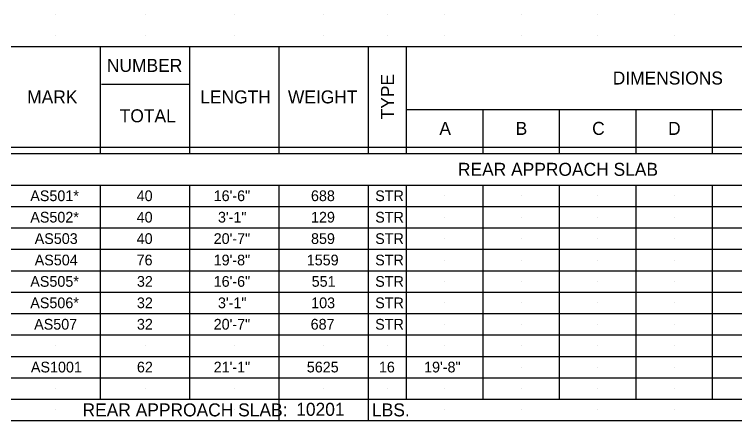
# Model space of a CAD drawing. Extents: x 0 to 34, y 0 to 22.
# Drawn here: x 16.8 to 26.21, y 9.38 to 14.69 of the extents above; entities that cross this region are included whole.
import ezdxf

# ---------------------------------------------------------------- set-up
doc = ezdxf.new("R2010")
doc.units = 0
doc.layers.add('BR_P_Gen_Text', color=7, linetype='Continuous')

msp = doc.modelspace()

# ---------------------------------------------------------------- linework, layer by layer
at = {"layer": 'BR_P_Gen_Text'}
for p, q in [((17.3435, 14.6926), (17.3435, 14.6926)), ((17.3435, 14.6926), (17.3435, 14.6926)), ((18.5102, 14.6926), (18.5102, 14.6926)), ((18.5102, 14.6926), (18.5102, 14.6926)), ((19.6769, 14.6926), (19.6769, 14.6926)), ((19.6769, 14.6926), (19.6769, 14.6926)), ((20.8437, 14.6927), (20.8437, 14.6927)), ((20.8437, 14.6927), (20.8437, 14.6927)), ((21.677, 14.6926), (21.677, 14.6926)), ((21.677, 14.6926), (21.677, 14.6926)), ((22.427, 14.6926), (22.427, 14.6926)), ((22.427, 14.6926), (22.427, 14.6926)), ((23.427, 14.6926), (23.427, 14.6926)), ((23.427, 14.6926), (23.427, 14.6926)), ((24.427, 14.6926), (24.427, 14.6926)), ((24.427, 14.6926), (24.427, 14.6926)), ((25.427, 14.6926), (25.427, 14.6926)), ((25.427, 14.6926), (25.427, 14.6926)), ((17.3435, 14.4126), (17.3435, 14.4126)), ((17.3435, 14.4126), (17.3435, 14.4126)), ((18.5102, 14.4126), (18.5102, 14.4126)), ((18.5102, 14.4126), (18.5102, 14.4126)), ((19.6769, 14.4126), (19.6769, 14.4126)), ((19.6769, 14.4126), (19.6769, 14.4126)), ((20.8436, 14.4127), (20.8436, 14.4127)), ((20.8437, 14.4127), (20.8437, 14.4127)), ((21.677, 14.4126), (21.677, 14.4126)), ((21.677, 14.4126), (21.677, 14.4126)), ((22.427, 14.4126), (22.427, 14.4126)), ((23.427, 14.4126), (23.427, 14.4126)), ((24.427, 14.4126), (24.427, 14.4126)), ((25.427, 14.4126), (25.427, 14.4126)), ((16.7602, 14.2725), (31.927, 14.2726)), ((17.9269, 12.8725), (17.9269, 14.2725)), ((19.0936, 12.8723), (19.0936, 14.2725)), ((20.2602, 12.8725), (20.2603, 14.2725)), ((21.427, 12.8726), (21.427, 14.2725)), ((21.927, 12.8726), (21.927, 14.2725)), ((17.9407, 13.7784), (19.0936, 13.7784)), ((21.927, 13.449), (28.927, 13.4491)), ((22.927, 12.8724), (22.927, 13.4491)), ((23.927, 12.8724), (23.927, 13.4491)), ((24.927, 12.8723), (24.927, 13.4491)), ((25.927, 12.8724), (25.927, 13.4491)), ((16.7602, 12.9548), (31.927, 12.9549)), ((16.7602, 12.8725), (31.927, 12.8725)), ((22.8436, 12.6666), (22.8436, 12.6666)), ((16.7602, 12.4608), (31.927, 12.4609)), ((17.9269, 9.6608), (17.9269, 12.4608)), ((19.0936, 9.6608), (19.0936, 12.4608)), ((20.2603, 9.3808), (20.2602, 12.4608)), ((21.427, 9.3808), (21.427, 12.4609)), ((21.927, 9.6608), (21.927, 12.4609)), ((22.9269, 9.6608), (22.927, 12.4608)), ((23.927, 9.6608), (23.927, 12.4608)), ((24.927, 9.6608), (24.927, 12.4608)), ((25.927, 9.6608), (25.927, 12.4608)), ((17.3435, 12.3208), (17.3435, 12.3208)), ((18.5102, 12.3208), (18.5102, 12.3208)), ((19.6769, 12.3209), (19.6769, 12.3209)), ((20.8437, 12.3209), (20.8437, 12.3209)), ((21.677, 12.3208), (21.677, 12.3208)), ((22.427, 12.3208), (22.427, 12.3208)), ((23.427, 12.3208), (23.427, 12.3208)), ((24.427, 12.3208), (24.427, 12.3208)), ((25.427, 12.3208), (25.427, 12.3208)), ((16.7602, 12.1808), (31.927, 12.1808)), ((17.3435, 12.0408), (17.3435, 12.0408)), ((18.5102, 12.0408), (18.5102, 12.0408)), ((19.6769, 12.0409), (19.6769, 12.0409)), ((20.8437, 12.0409), (20.8437, 12.0409)), ((21.677, 12.0408), (21.677, 12.0408)), ((22.427, 12.0408), (22.427, 12.0408)), ((23.427, 12.0408), (23.427, 12.0408)), ((24.427, 12.0408), (24.427, 12.0408)), ((25.427, 12.0408), (25.427, 12.0408)), ((16.7602, 11.9008), (31.927, 11.9008)), ((17.3435, 11.7608), (17.3435, 11.7608)), ((18.5102, 11.7608), (18.5102, 11.7608)), ((19.6769, 11.7608), (19.6769, 11.7608)), ((20.8437, 11.7609), (20.8437, 11.7609)), ((21.677, 11.7608), (21.677, 11.7608)), ((22.427, 11.7608), (22.427, 11.7608)), ((23.427, 11.7608), (23.427, 11.7608)), ((24.427, 11.7608), (24.427, 11.7608)), ((25.427, 11.7608), (25.427, 11.7608)), ((16.7602, 11.6208), (31.927, 11.6208)), ((17.3435, 11.4808), (17.3435, 11.4808)), ((22.427, 11.4808), (22.427, 11.4808)), ((23.427, 11.4808), (23.427, 11.4808)), ((24.427, 11.4808), (24.427, 11.4808)), ((25.427, 11.4808), (25.427, 11.4808)), ((16.7602, 11.3408), (31.927, 11.3408)), ((17.3435, 11.2008), (17.3435, 11.2008)), ((18.5102, 11.2008), (18.5102, 11.2008)), ((19.6769, 11.2008), (19.6769, 11.2008)), ((20.8437, 11.2009), (20.8437, 11.2009)), ((21.677, 11.2008), (21.677, 11.2008)), ((22.427, 11.2008), (22.427, 11.2008)), ((23.427, 11.2008), (23.427, 11.2008)), ((24.427, 11.2008), (24.427, 11.2008)), ((25.427, 11.2008), (25.427, 11.2008)), ((16.7602, 11.0608), (31.927, 11.0608)), ((17.3435, 10.9208), (17.3435, 10.9208)), ((18.5102, 10.9208), (18.5102, 10.9208)), ((19.6769, 10.9208), (19.6769, 10.9208)), ((20.8437, 10.9209), (20.8437, 10.9209)), ((21.677, 10.9208), (21.677, 10.9208)), ((22.427, 10.9208), (22.427, 10.9208)), ((23.427, 10.9208), (23.427, 10.9208)), ((24.427, 10.9208), (24.427, 10.9208)), ((25.427, 10.9208), (25.427, 10.9208)), ((16.7602, 10.7808), (31.927, 10.7809)), ((17.3435, 10.6408), (17.3435, 10.6408)), ((18.5102, 10.6408), (18.5102, 10.6408)), ((19.6769, 10.6408), (19.6769, 10.6408)), ((20.8437, 10.6409), (20.8437, 10.6409)), ((21.677, 10.6408), (21.677, 10.6408)), ((22.427, 10.6408), (22.427, 10.6408)), ((23.427, 10.6408), (23.427, 10.6408)), ((24.427, 10.6408), (24.427, 10.6408)), ((25.427, 10.6408), (25.427, 10.6408)), ((16.7602, 10.5008), (31.927, 10.5009)), ((17.3435, 10.3608), (17.3435, 10.3608)), ((17.3435, 10.3608), (17.3435, 10.3608)), ((18.5102, 10.3608), (18.5102, 10.3608)), ((18.5102, 10.3608), (18.5102, 10.3608)), ((19.6769, 10.3608), (19.6769, 10.3608)), ((19.6769, 10.3608), (19.6769, 10.3608)), ((20.8437, 10.3609), (20.8437, 10.3609)), ((20.8437, 10.3609), (20.8437, 10.3609)), ((21.677, 10.3608), (21.677, 10.3608)), ((21.677, 10.3608), (21.677, 10.3608)), ((22.427, 10.3608), (22.427, 10.3608)), ((22.427, 10.3608), (22.427, 10.3608)), ((23.427, 10.3608), (23.427, 10.3608)), ((23.427, 10.3608), (23.427, 10.3608)), ((24.427, 10.3608), (24.427, 10.3608)), ((24.427, 10.3608), (24.427, 10.3608)), ((25.427, 10.3608), (25.427, 10.3608)), ((25.427, 10.3608), (25.427, 10.3608)), ((16.7602, 10.2208), (31.927, 10.2209)), ((17.3435, 10.0808), (17.3435, 10.0808)), ((17.3435, 10.0808), (17.3435, 10.0808)), ((18.5102, 10.0808), (18.5102, 10.0808)), ((18.5102, 10.0808), (18.5102, 10.0808)), ((19.6769, 10.0808), (19.6769, 10.0808)), ((19.6769, 10.0808), (19.6769, 10.0808)), ((20.8437, 10.0809), (20.8437, 10.0809)), ((20.8437, 10.0809), (20.8437, 10.0809)), ((21.677, 10.0808), (21.677, 10.0808)), ((21.677, 10.0808), (21.677, 10.0808)), ((22.427, 10.0808), (22.427, 10.0808)), ((22.427, 10.0808), (22.427, 10.0808)), ((23.427, 10.0808), (23.427, 10.0808)), ((23.427, 10.0808), (23.427, 10.0808)), ((24.427, 10.0808), (24.427, 10.0808)), ((24.427, 10.0808), (24.427, 10.0808)), ((25.427, 10.0808), (25.427, 10.0808)), ((25.427, 10.0808), (25.427, 10.0808)), ((16.7602, 9.9408), (31.927, 9.9409)), ((17.3435, 9.8008), (17.3435, 9.8008)), ((18.5102, 9.8008), (18.5102, 9.8008)), ((19.6769, 9.8008), (19.6769, 9.8008)), ((20.8437, 9.8009), (20.8437, 9.8009)), ((21.677, 9.8008), (21.677, 9.8008)), ((22.427, 9.8008), (22.427, 9.8008)), ((23.427, 9.8008), (23.427, 9.8008)), ((24.427, 9.8008), (24.427, 9.8008)), ((25.427, 9.8008), (25.427, 9.8008)), ((16.7602, 9.6608), (31.927, 9.6608)), ((17.3435, 9.5208), (17.3435, 9.5208)), ((18.5102, 9.5208), (18.5102, 9.5208)), ((19.6769, 9.5208), (19.6769, 9.5208)), ((20.8437, 9.5209), (20.8437, 9.5209)), ((21.677, 9.5208), (21.677, 9.5208)), ((22.427, 9.5208), (22.427, 9.5208)), ((23.427, 9.5208), (23.427, 9.5208)), ((24.427, 9.5208), (24.427, 9.5208)), ((25.427, 9.5208), (25.427, 9.5208)), ((16.7602, 9.3808), (31.927, 9.3808))]:
    msp.add_line(p, q, dxfattribs=at)

# ---------------------------------------------------------------- texts
for s, height, p in [('NUMBER', 0.17, (18.0101, 13.9404)), ('DIMENSIONS', 0.17, (24.6212, 13.7758)), ('MARK', 0.17, (16.9678, 13.5287)), ('LENGTH', 0.17, (19.2303, 13.5287)), ('WEIGHT', 0.17, (20.3758, 13.5287)), ('TOTAL', 0.17, (18.1771, 13.2816)), ('A', 0.17, (22.3553, 13.117)), ('B', 0.17, (23.3522, 13.117)), ('C', 0.17, (24.3522, 13.117)), ('D', 0.17, (25.3449, 13.117)), ('REAR APPROACH SLAB', 0.17, (22.5978, 12.5817)), ('AS501*', 0.14, (17.0085, 12.2508)), ('40', 0.14, (18.3988, 12.2508)), ('16\'-6"', 0.14, (19.4055, 12.2508)), ('688', 0.14, (20.6769, 12.2508)), ('STR', 0.14, (21.5168, 12.2508)), ('AS502*', 0.14, (17.0085, 11.9708)), ('40', 0.14, (18.3988, 11.9708)), ('3\'-1"', 0.14, (19.4614, 11.9708)), ('129', 0.14, (20.6777, 11.9708)), ('STR', 0.14, (21.5168, 11.9708)), ('AS503', 0.14, (17.0662, 11.6908)), ('40', 0.14, (18.3988, 11.6908)), ('20\'-7"', 0.14, (19.4055, 11.6908)), ('859', 0.14, (20.6777, 11.6908)), ('STR', 0.14, (21.5168, 11.6908)), ('AS504', 0.14, (17.0662, 11.4108)), ('76', 0.14, (18.3982, 11.4108)), ('19\'-8"', 0.14, (19.4055, 11.4108)), ('1559', 0.14, (20.6218, 11.4108)), ('STR', 0.14, (21.5168, 11.4108)), ('AS505*', 0.14, (17.0085, 11.1308)), ('32', 0.14, (18.4021, 11.1308)), ('16\'-6"', 0.14, (19.4055, 11.1308)), ('551', 0.14, (20.6861, 11.1308)), ('STR', 0.14, (21.5168, 11.1308)), ('AS506*', 0.14, (17.0085, 10.8508)), ('32', 0.14, (18.4021, 10.8508)), ('3\'-1"', 0.14, (19.4614, 10.8508)), ('103', 0.14, (20.68, 10.8508)), ('STR', 0.14, (21.5168, 10.8508)), ('AS507', 0.14, (17.059, 10.5708)), ('32', 0.14, (18.4021, 10.5708)), ('20\'-7"', 0.14, (19.4055, 10.5708)), ('687', 0.14, (20.6728, 10.5708)), ('STR', 0.14, (21.5168, 10.5708)), ('AS1001', 0.14, (17.0164, 10.0108)), ('62', 0.14, (18.4021, 10.0108)), ('21\'-1"', 0.14, (19.4055, 10.0108)), ('5625', 0.14, (20.6225, 10.0108)), ('16', 0.14, (21.5649, 10.0108)), ('19\'-8"', 0.14, (22.1555, 10.0108)), ('REAR APPROACH SLAB:', 0.17, (17.6913, 9.4358)), ('10201', 0.17, (20.4841, 9.4432)), ('LBS.', 0.17, (21.4752, 9.4358))]:
    msp.add_text(s, height=height, dxfattribs=at).set_placement(p)
msp.add_text('TYPE', height=0.17, rotation=90, dxfattribs=at).set_placement((21.762, 13.3199))

doc.saveas('drawing.dxf')
